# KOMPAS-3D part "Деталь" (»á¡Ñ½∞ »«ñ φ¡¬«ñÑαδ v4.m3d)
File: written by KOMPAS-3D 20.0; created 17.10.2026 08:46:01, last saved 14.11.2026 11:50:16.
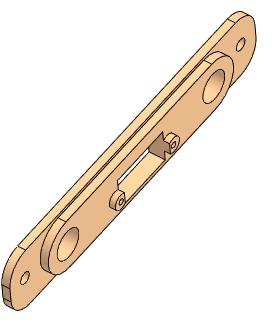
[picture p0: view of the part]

Document properties: Полное имя файла: D:\myProjects\Progect_esp32\box_compas\корпус\панель кнопоr 2bt v4.m3d

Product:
- Part/product: Деталь
    Масса: 0.0264939

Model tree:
1. Эскиз:1
2. Элемент выдавливания:1
     Расстояние 1 = 2
3. Эскиз:5  (with: Элемент выдавливания:1)
4. Элемент выдавливания:6
     Расстояние 2 = 2
5. Эскиз:6  (with: Элемент выдавливания:1)
6. Элемент выдавливания:7
     Расстояние 1 = 2
7. Эскиз:7  (with: Элемент выдавливания:7, Элемент выдавливания:1)
8. Элемент выдавливания:8
     Расстояние 2 = 4
9. Массив по сетке:1  (with: Элемент выдавливания:8, Эскиз:7)  (2 pattern instances)
     Шаг 1 = 50; Угол раствора = 90
10. Эскиз:10  (with: Элемент выдавливания:1, Элемент выдавливания:8)
11. Элемент выдавливания:18
     Расстояние 2 = 4
12. Эскиз:11  (with: Элемент выдавливания:7, Элемент выдавливания:18)
13. Элемент выдавливания:19
     Расстояние 1 = 1.5
14. Эскиз:12  (with: Элемент выдавливания:19)
15. Элемент выдавливания:20
     Расстояние 2 = 4
16. Элемент выдавливания:23  (with: Элемент выдавливания:1)
     Расстояние 2 = 0.5
17. Элемент выдавливания:24  (with: Элемент выдавливания:1)
     Расстояние 2 = 0.5
18. Элемент выдавливания:25  (with: Элемент выдавливания:23)
     Расстояние 1 = 1
19. Скругление:10  (with: Элемент выдавливания:24, Элемент выдавливания:25)
     Радиус = 6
